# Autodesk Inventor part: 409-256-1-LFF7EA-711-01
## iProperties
Created: 2010-06
Part Number: 409-256-1-LFF7EA-711-01
Material: Sch40 CS PIPE SEAMLESS
Description: PIPE
Document SubType Name: Modeling
Designer: S. Boerckel
Engineer: Steve Boerckel
Mass: 4070.39 g
Surface Area: 1763.67 cm^2
Volume: 518.521 cm^3
Density: 7.85 g/cm^3
Cost Center: 4"
SMR: =<COST CENTER> - <Material>
Length: 9.969 in
Title: 3"
Author: S. Boerckel
Revision Number: A
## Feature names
1. Extrusion1
